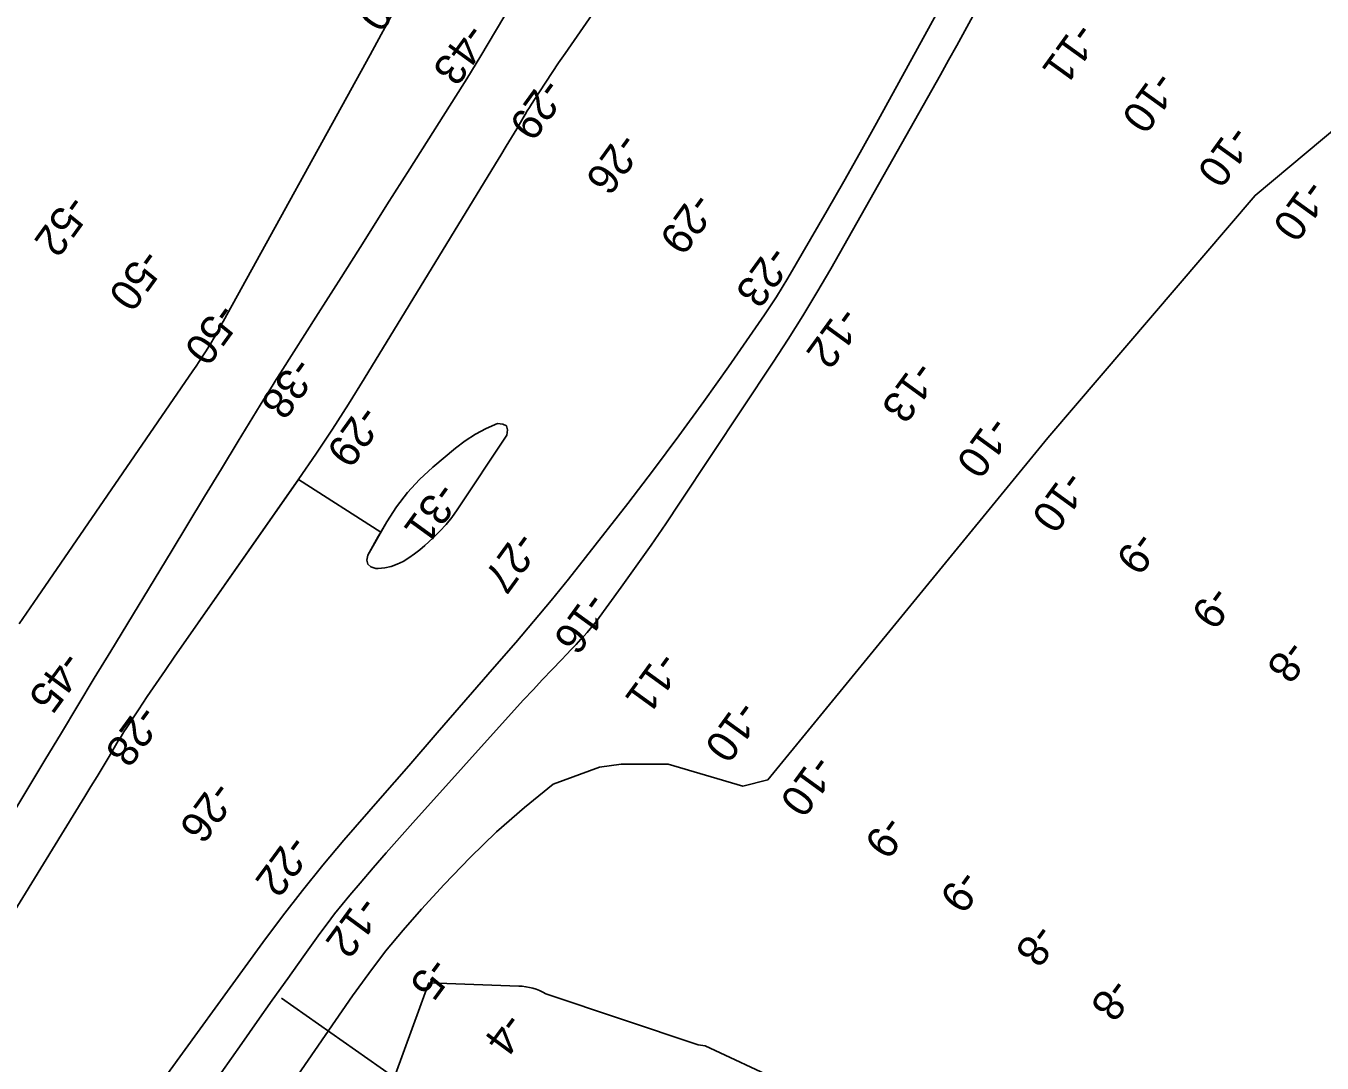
# Model space of a CAD drawing. Extents: x 3879599 to 3900814, y 146526 to 168888.
# Drawn here: x 3895080 to 3896475, y 159864 to 160981 of the extents above; entities that cross this region are included whole.
import ezdxf

# ---------------------------------------------------------------- set-up
doc = ezdxf.new("R2010")
doc.units = 0
for name, color, linetype in [('V-LEVE-TOET', 7, 'Continuous'), ('V-RIVR-RANG', 7, 'Continuous'), ('V-TOPO-DPTH', 7, 'Continuous'), ('V-TOPO-MAJR', 7, 'Continuous'), ('V-TOPO-MINR', 7, 'Continuous')]:
    doc.layers.add(name, color=color, linetype=linetype)

msp = doc.modelspace()

# ---------------------------------------------------------------- linework, layer by layer
at = {"layer": 'V-LEVE-TOET'}
msp.add_lwpolyline([(3896148.1, 159373.2), (3895979.9, 159492.3), (3895775.6, 159636.8), (3895541.2, 159803.7), (3895355.5, 159934.1)], dxfattribs=at)
at = {"layer": 'V-TOPO-DPTH'}
for points in [[(3895804.1, 161158.6), (3895660.6, 160950.9), (3895653.7, 160940.7), (3895646.8, 160930.5), (3895640, 160920.2), (3895633.2, 160909.8), (3895624.5, 160896.4), (3895622.2, 160892.7), (3895619.9, 160889.1), (3895617.7, 160885.4), (3895615.5, 160881.7), (3895608.6, 160870), (3895602.9, 160860.5), (3895597.2, 160851), (3895591.5, 160841.5), (3895585.7, 160832), (3895444.5, 160600.7), (3895427.5, 160573.5), (3895410.2, 160546.5), (3895392.4, 160519.8), (3895374.2, 160493.3), (3895239.9, 160301.1), (3895230.1, 160287), (3895220.4, 160272.9), (3895210.9, 160258.7), (3895201.4, 160244.5), (3895188.8, 160225.5), (3895185.7, 160220.7), (3895182.7, 160215.9), (3895179.7, 160211.1), (3895176.7, 160206.2), (3895169.7, 160194.3), (3895163.3, 160183.6), (3895156.8, 160172.8), (3895150.3, 160162), (3895143.7, 160151.3), (3895009.8, 159933.8)], [(3895462.4, 160435.8), (3895373.5, 160492.3), (3895374.2, 160493.3), (3895392.4, 160519.8), (3895410.2, 160546.5), (3895427.5, 160573.5), (3895444.5, 160600.7), (3895585.7, 160832), (3895591.5, 160841.5), (3895597.2, 160851), (3895602.9, 160860.5), (3895608.6, 160870), (3895615.5, 160881.7), (3895617.7, 160885.4), (3895619.9, 160889.1), (3895622.2, 160892.7), (3895624.5, 160896.4), (3895633.2, 160909.8), (3895640, 160920.2), (3895646.8, 160930.5), (3895653.7, 160940.7), (3895660.6, 160950.9), (3895804.1, 161158.6)], [(3894999, 160021.8), (3895100.7, 160190.5), (3895118.4, 160219.9), (3895136.1, 160249.2), (3895153.9, 160278.5), (3895171.6, 160307.8), (3895236.5, 160414.6), (3895254.5, 160444.3), (3895272.6, 160474.1), (3895290.8, 160503.8), (3895308.9, 160533.6), (3895336.5, 160578.7), (3895340.9, 160585.9), (3895345.3, 160593), (3895349.7, 160600.1), (3895354.2, 160607.1), (3895394.7, 160670.9), (3895419.5, 160709.9), (3895444.2, 160748.9), (3895468.9, 160787.9), (3895493.6, 160826.9), (3895549.8, 160915.7), (3895554.9, 160923.8), (3895559.9, 160931.9), (3895564.9, 160940.1), (3895569.8, 160948.3), (3895602.5, 161003.3)], [(3895602.5, 161003.3), (3895569.8, 160948.3), (3895564.9, 160940.1), (3895559.9, 160931.9), (3895554.9, 160923.8), (3895549.8, 160915.7), (3895493.6, 160826.9), (3895468.9, 160787.9), (3895444.2, 160748.9), (3895419.5, 160709.9), (3895394.7, 160670.9), (3895354.2, 160607.1), (3895349.7, 160600.1), (3895345.3, 160593), (3895340.9, 160585.9), (3895336.5, 160578.7), (3895308.9, 160533.6), (3895290.8, 160503.8), (3895272.6, 160474.1), (3895254.5, 160444.3), (3895236.5, 160414.6), (3895171.6, 160307.8), (3895153.9, 160278.5), (3895136.1, 160249.2), (3895118.4, 160219.9), (3895100.7, 160190.5), (3894999, 160021.8)], [(3896063.9, 161000.1), (3895995.7, 160875.9), (3895978.2, 160844.5), (3895960.6, 160813.2), (3895942.8, 160782), (3895924.8, 160750.9), (3895900.3, 160709), (3895894.3, 160699), (3895888.1, 160689), (3895881.7, 160679.3), (3895875.2, 160669.6), (3895836.4, 160613.8), (3895810, 160576.5), (3895783.2, 160539.5), (3895755.9, 160502.9), (3895728.1, 160466.7), (3895682.6, 160408.3), (3895664.3, 160385.2), (3895645.7, 160362.2), (3895626.8, 160339.6), (3895607.6, 160317.1), (3895584.7, 160290.8), (3895553.9, 160255.3), (3895523.1, 160219.9), (3895492.3, 160184.4), (3895461.5, 160148.9), (3895422.6, 160104.1), (3895400, 160077.3), (3895377.8, 160050.1), (3895356.3, 160022.3), (3895335.4, 159994.2), (3895216.6, 159830.6)], [(3896063.9, 161000.1), (3895995.7, 160875.9), (3895978.2, 160844.5), (3895960.6, 160813.2), (3895942.8, 160782), (3895924.8, 160750.9), (3895900.3, 160709), (3895894.3, 160699), (3895888.1, 160689), (3895881.7, 160679.3), (3895875.2, 160669.6), (3895836.4, 160613.8), (3895810, 160576.5), (3895783.2, 160539.5), (3895755.9, 160502.9), (3895728.1, 160466.7), (3895682.6, 160408.3), (3895664.3, 160385.2), (3895645.7, 160362.2), (3895626.8, 160339.6), (3895607.6, 160317.1), (3895584.7, 160290.8), (3895553.9, 160255.3), (3895523.1, 160219.9), (3895492.3, 160184.4), (3895461.5, 160148.9), (3895422.6, 160104.1), (3895400, 160077.3), (3895377.8, 160050.1), (3895356.3, 160022.3), (3895335.4, 159994.2), (3895216.6, 159830.6)], [(3895373, 159851.3), (3895431.8, 159936.6), (3895449.3, 159960.8), (3895467.4, 159984.6), (3895486.4, 160007.5), (3895506.1, 160029.9), (3895530.6, 160056.6), (3895558.3, 160085.4), (3895586.9, 160113.1), (3895616.9, 160139.3), (3895647.9, 160164.5), (3895697.5, 160182.7), (3895721, 160186), (3895771.5, 160186), (3895852.1, 160162.5), (3895879, 160169.2), (3896180.4, 160537.3), (3896403.4, 160798.1), (3896495.6, 160875.2)], [(3895448.2, 160401.3), (3895451.7, 160398.4), (3895456.8, 160396.5), (3895459.3, 160396.6), (3895466.5, 160397.3), (3895473.4, 160398.7), (3895480, 160401.2), (3895486.4, 160404.3), (3895492.5, 160408.2), (3895498.5, 160412.3), (3895504.2, 160416.8), (3895509.7, 160421.5), (3895518.7, 160429.8), (3895525.8, 160436.7), (3895532.5, 160443.9), (3895538.6, 160451.6), (3895544.4, 160459.7), (3895597.8, 160540.2), (3895598.5, 160545.9), (3895597.4, 160550.1), (3895593.5, 160552.1), (3895587.8, 160552.7), (3895575.7, 160547.3), (3895564.1, 160541.2), (3895553.1, 160534), (3895542.6, 160526), (3895518.1, 160505.5), (3895504, 160492.4), (3895490.9, 160478.4), (3895479.3, 160463.1), (3895468.8, 160446.9), (3895448.2, 160411), (3895447.4, 160405.7), (3895448.2, 160401.3)], [(3895448.2, 160401.3), (3895451.7, 160398.4), (3895456.8, 160396.5), (3895459.3, 160396.6), (3895466.5, 160397.3), (3895473.4, 160398.7), (3895480, 160401.2), (3895486.4, 160404.3), (3895492.5, 160408.2), (3895498.5, 160412.3), (3895504.2, 160416.8), (3895509.7, 160421.5), (3895518.7, 160429.8), (3895525.8, 160436.7), (3895532.5, 160443.9), (3895538.6, 160451.6), (3895544.4, 160459.7), (3895597.8, 160540.2), (3895598.5, 160545.9), (3895597.4, 160550.1), (3895593.5, 160552.1), (3895587.8, 160552.7), (3895575.7, 160547.3), (3895564.1, 160541.2), (3895553.1, 160534), (3895542.6, 160526), (3895518.1, 160505.5), (3895504, 160492.4), (3895490.9, 160478.4), (3895479.3, 160463.1), (3895468.8, 160446.9), (3895462.4, 160435.8)], [(3894948.8, 159839.8), (3894969.6, 159870.8), (3894989.9, 159902.2), (3895009.8, 159933.8), (3895143.7, 160151.3), (3895150.3, 160162), (3895156.8, 160172.8), (3895163.3, 160183.6), (3895169.7, 160194.3), (3895176.7, 160206.2), (3895179.7, 160211.1), (3895182.7, 160215.9), (3895185.7, 160220.7), (3895188.8, 160225.5), (3895201.4, 160244.5), (3895210.9, 160258.7), (3895220.4, 160272.9), (3895230.1, 160287), (3895239.9, 160301.1), (3895370.4, 160487.8), (3895373.5, 160492.3), (3895462.4, 160435.8), (3895459.6, 160430.9)], [(3895459.6, 160430.9), (3895448.2, 160411), (3895447.4, 160405.7), (3895448.2, 160401.3)]]:
    msp.add_lwpolyline(points, dxfattribs=at)
at = {"layer": 'V-TOPO-MAJR'}
msp.add_lwpolyline([(3895073, 160337.1), (3895092.6, 160365.9), (3895260.1, 160609.5), (3895263.5, 160614.5), (3895266.8, 160619.5), (3895270.1, 160624.6), (3895273.4, 160629.7), (3895277.9, 160636.8), (3895278.9, 160638.3), (3895280.7, 160641.4), (3895281.6, 160642.9), (3895284.2, 160647.4), (3895286.3, 160651.1), (3895288.4, 160654.9), (3895290.5, 160658.7), (3895292.6, 160662.5), (3895450.7, 160949.6), (3895462.6, 160971.2), (3895474.6, 160992.9)], dxfattribs=at)
at = {"layer": 'V-TOPO-MINR'}
for points in [[(3895009.8, 159933.8), (3895143.7, 160151.3), (3895150.3, 160162), (3895156.8, 160172.8), (3895163.3, 160183.6), (3895169.7, 160194.3), (3895176.7, 160206.2), (3895179.7, 160211.1), (3895182.7, 160215.9), (3895185.7, 160220.7), (3895188.8, 160225.5), (3895201.4, 160244.5), (3895210.9, 160258.7), (3895220.4, 160272.9), (3895230.1, 160287), (3895239.9, 160301.1), (3895374.2, 160493.3), (3895392.4, 160519.8), (3895410.2, 160546.5), (3895427.5, 160573.5), (3895444.5, 160600.7), (3895585.7, 160832), (3895591.5, 160841.5), (3895597.2, 160851), (3895602.9, 160860.5), (3895608.6, 160870), (3895615.5, 160881.7), (3895617.7, 160885.4), (3895619.9, 160889.1), (3895622.2, 160892.7), (3895624.5, 160896.4), (3895633.2, 160909.8), (3895640, 160920.2), (3895646.8, 160930.5), (3895653.7, 160940.7), (3895660.6, 160950.9), (3895804.1, 161158.6)], [(3894999, 160021.8), (3895100.7, 160190.5), (3895118.4, 160219.9), (3895136.1, 160249.2), (3895153.9, 160278.5), (3895171.6, 160307.8), (3895236.5, 160414.6), (3895254.5, 160444.3), (3895272.6, 160474.1), (3895290.8, 160503.8), (3895308.9, 160533.6), (3895336.5, 160578.7), (3895340.9, 160585.9), (3895345.3, 160593), (3895349.7, 160600.1), (3895354.2, 160607.1), (3895394.7, 160670.9), (3895419.5, 160709.9), (3895444.2, 160748.9), (3895468.9, 160787.9), (3895493.6, 160826.9), (3895549.8, 160915.7), (3895554.9, 160923.8), (3895559.9, 160931.9), (3895564.9, 160940.1), (3895569.8, 160948.3), (3895602.5, 161003.3)], [(3895216.6, 159830.6), (3895335.4, 159994.2), (3895356.3, 160022.3), (3895377.8, 160050.1), (3895400, 160077.3), (3895422.6, 160104.1), (3895461.5, 160148.9), (3895492.3, 160184.4), (3895523.1, 160219.9), (3895553.9, 160255.3), (3895584.7, 160290.8), (3895607.6, 160317.1), (3895626.8, 160339.6), (3895645.7, 160362.2), (3895664.3, 160385.2), (3895682.6, 160408.3), (3895728.1, 160466.7), (3895755.9, 160502.9), (3895783.2, 160539.5), (3895810, 160576.5), (3895836.4, 160613.8), (3895875.2, 160669.6), (3895881.7, 160679.3), (3895888.1, 160689), (3895894.3, 160699), (3895900.3, 160709), (3895924.8, 160750.9), (3895942.8, 160782), (3895960.6, 160813.2), (3895978.2, 160844.5), (3895995.7, 160875.9), (3896063.9, 161000.1)], [(3895223.8, 159759.2), (3895312.6, 159885.5), (3895329, 159908.9), (3895345.5, 159932.2), (3895362.1, 159955.4), (3895378.7, 159978.7), (3895396.7, 160003.7), (3895404.5, 160014.3), (3895412.5, 160024.8), (3895420.7, 160035), (3895429.1, 160045.2), (3895440, 160057.9), (3895454, 160074.3), (3895468.2, 160090.6), (3895482.4, 160106.7), (3895496.8, 160122.8), (3895605.9, 160244), (3895615.9, 160255.1), (3895626.1, 160266.1), (3895636.3, 160277), (3895646.6, 160287.8), (3895656.8, 160298.4), (3895662.1, 160303.9), (3895667.3, 160309.4), (3895672.5, 160314.9), (3895677.7, 160320.5), (3895680.9, 160323.9), (3895684.4, 160327.8), (3895687.8, 160331.8), (3895691.1, 160335.9), (3895694.3, 160340.1), (3895720.9, 160376.6), (3895737.1, 160399.1), (3895753.2, 160421.9), (3895769, 160444.8), (3895784.5, 160467.9), (3895884.7, 160618.7), (3895900.8, 160643.5), (3895916.5, 160668.4), (3895931.7, 160693.7), (3895946.5, 160719.3), (3896064.6, 160928), (3896073.4, 160943.7), (3896082.2, 160959.5), (3896090.9, 160975.3), (3896099.6, 160991.1)], [(3895373, 159851.3), (3895431.8, 159936.6), (3895449.3, 159960.8), (3895467.4, 159984.6), (3895486.4, 160007.5), (3895506.1, 160029.9), (3895530.6, 160056.6), (3895558.3, 160085.4), (3895586.9, 160113.1), (3895616.9, 160139.3), (3895647.9, 160164.5), (3895697.5, 160182.7), (3895721, 160186), (3895771.5, 160186), (3895852.1, 160162.5), (3895879, 160169.2), (3896180.4, 160537.3), (3896403.4, 160798.1), (3896495.6, 160875.2)], [(3895448.2, 160401.3), (3895451.7, 160398.4), (3895456.8, 160396.5), (3895459.3, 160396.6), (3895466.5, 160397.3), (3895473.4, 160398.7), (3895480, 160401.2), (3895486.4, 160404.3), (3895492.5, 160408.2), (3895498.5, 160412.3), (3895504.2, 160416.8), (3895509.7, 160421.5), (3895518.7, 160429.8), (3895525.8, 160436.7), (3895532.5, 160443.9), (3895538.6, 160451.6), (3895544.4, 160459.7), (3895597.8, 160540.2), (3895598.5, 160545.9), (3895597.4, 160550.1), (3895593.5, 160552.1), (3895587.8, 160552.7), (3895575.7, 160547.3), (3895564.1, 160541.2), (3895553.1, 160534), (3895542.6, 160526), (3895518.1, 160505.5), (3895504, 160492.4), (3895490.9, 160478.4), (3895479.3, 160463.1), (3895468.8, 160446.9), (3895448.2, 160411), (3895447.4, 160405.7), (3895448.2, 160401.3)], [(3895478.2, 159852.4), (3895514, 159950.6), (3895610.7, 159947.2), (3895614.6, 159947), (3895618.4, 159946.5), (3895622.2, 159945.8), (3895625.9, 159945), (3895629.6, 159943.8), (3895633.1, 159942.5), (3895636.5, 159940.7), (3895639.8, 159938.8), (3895803.7, 159884.1), (3895811.5, 159882.8), (3895892.8, 159844.7)]]:
    msp.add_lwpolyline(points, dxfattribs=at)

# ---------------------------------------------------------------- texts
at = {"layer": 'V-RIVR-RANG'}
for s, rotation, p in [('-50', 234.121, (3895473.1, 161044)), ('-43', 234.121, (3895554.8, 160985.8)), ('-11', 234.2083, (3896210.6, 160986.7)), ('-10', 234.2083, (3896296.2, 160934.4)), ('-29', 234.121, (3895637.1, 160926.8)), ('-10', 234.2083, (3896377.4, 160876.1)), ('-26', 234.121, (3895719.4, 160868.2)), ('-10', 234.2083, (3896458.7, 160817.8)), ('-52', 234.198, (3895125.7, 160801.4)), ('-29', 233.9783, (3895798.9, 160803.8)), ('-50', 234.198, (3895205.6, 160743)), ('-23', 233.9783, (3895880.9, 160746.6)), ('-50', 234.198, (3895287.1, 160684.7)), ('-12', 233.9783, (3895956.8, 160680.9)), ('-38', 234.198, (3895369.4, 160626.6)), ('-13', 233.9783, (3896038, 160622.5)), ('-29', 234.198, (3895440.4, 160574.9)), ('-10', 233.9783, (3896118.3, 160563)), ('-10', 233.9783, (3896199.4, 160504.4)), ('-31', 234.0583, (3895523.7, 160492.1)), ('-27', 234.0583, (3895608.8, 160439.1)), ('-9', 233.9783, (3896275.6, 160439.1)), ('-16', 234.0583, (3895684.9, 160373.7)), ('-9', 233.9783, (3896356.6, 160380.5)), ('-8', 233.9783, (3896437.9, 160322.3)), ('-45', 233.823, (3895119.9, 160310.1)), ('-11', 234.0583, (3895761.9, 160309.6)), ('-28', 233.823, (3895202.5, 160252.3)), ('-10', 234.0583, (3895847.4, 160257.1)), ('-10', 234.0583, (3895928.5, 160198.6)), ('-26', 233.6783, (3895282.5, 160170.4)), ('-9', 234.0583, (3896004.8, 160133.5)), ('-22', 233.6783, (3895364, 160112.4)), ('-9', 234.0583, (3896085.9, 160075)), ('-12', 233.6783, (3895439.7, 160046.6)), ('-8', 234.0583, (3896167.2, 160016.8)), ('-5', 233.6783, (3895515.6, 159981)), ('-8', 234.0583, (3896248.3, 159958.3)), ('-4', 233.6783, (3895595.8, 159921.2))]:
    msp.add_text(s, height=33.5, rotation=rotation, dxfattribs=at).set_placement(p)

doc.saveas('drawing.dxf')
